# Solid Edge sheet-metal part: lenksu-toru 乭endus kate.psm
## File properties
Title: lenksu-toru ühendus kate
Author: Stella-Marii
Template: Iso Metric Sheet Metal.psm
Last saved by: Stella-Marii
Revision: 9
Application: Solid Edge
Density: 1024,000 kg/m^3
Accuracy: 0,990
Material Thickness: 1,50 mm
Bend Radius: 1,00 mm
Relief Width: 1,00 mm
Relief Length: 0,00 mm
Neutral Factor: 0,330
Minimum Arc Length: 0,10 mm
Deviational Tolerance: 0,10 mm
Username: Stella-Marii
Document Number: 25
Material: ABS Plastic, high impact
Face Style: Red
Fill Style: ANSI34(Plastic)
Virtual Style: Red (Shiny)
Grouping: Non-metals\Plastics
LibraryName: Materials
Coef. of Thermal Exp: 9e-05
Thermal Conductivity: 0.2
Specific Heat: 0.0
Modulus of Elasticity: 1378951400.0
Poisson's Ratio: 0.4
Yield Stress: 31026406.5
Ultimate Stress: 0.0
Elongation: 0.0
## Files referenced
..\scooter.asm
@C:\Users\Stella-Marii\DATA\KOOL\Solid Edge - scooter\scooter.asm
C:\Users\Stella-Marii\DATA\KOOL\Solid Edge - scooter\lenksu-toru ühendus.psm
hendus.psm
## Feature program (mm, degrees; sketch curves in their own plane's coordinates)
base contour flange "ContourFlange_1"
sheet metal cutout "SheetMetalCutout_1"
sheet metal cutout "SheetMetalCutout_2"
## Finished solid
Body 1: solid body, 46 faces, 126 edges, 80 vertices.
  Faces by surface: swept 22, plane 19, cylinder 3, spline 2
  Edges by curve: line 59, spline 55, circle 6, intersection 4, ellipse 2
Bounding box of the edges (mm; curved faces can reach further): 70.500 x 47.000 x 7.693, from (-47, -23.5, -6.1928) to (23.5, 23.5, 1.5).
Cylindrical faces by radius (mm): R1 x1, R2.5 x1, R23.5 x1
Planar faces by outward normal: +x 2, +y 2, +z 1, -x 3, -y 4, -z 1, oblique 6
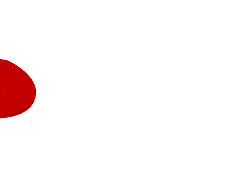
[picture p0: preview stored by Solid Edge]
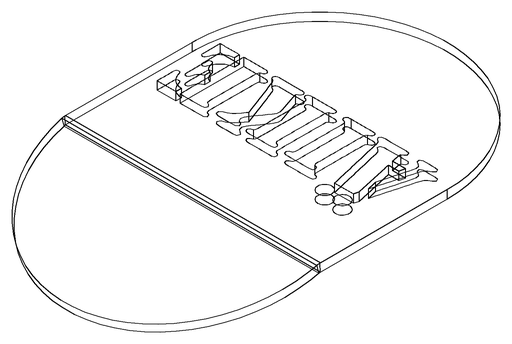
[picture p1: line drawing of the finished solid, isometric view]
